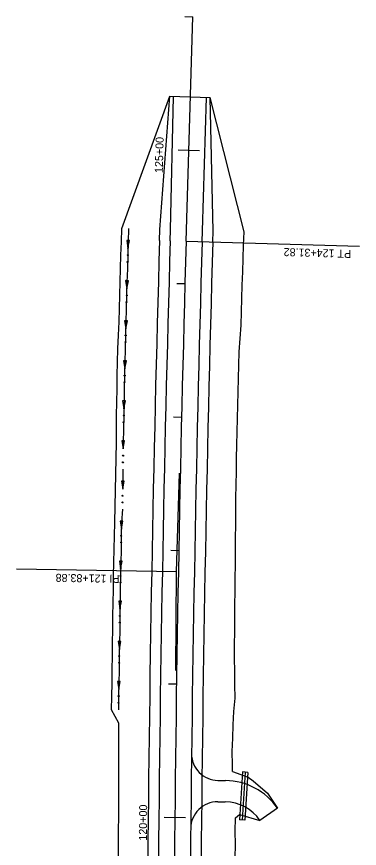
# Model space of a CAD drawing. Extents: x 1441466 to 1476381, y 2042742 to 2057194.
# Drawn here: x 1446002 to 1446259, y 2044733 to 2045357 of the extents above; entities that cross this region are included whole.
import ezdxf

# ---------------------------------------------------------------- set-up
doc = ezdxf.new("R2010")
doc.units = 0
for name, color, linetype in [('Level 43', 7, 'Continuous'), ('R_Horz Alg', 7, 'Continuous'), ('R_Horz Alg Annot', 7, 'Continuous'), ('R_Horz Alg Stationing', 7, 'Continuous'), ('R_Proposed Const Limits', 7, 'Continuous'), ('R_Proposed Road', 7, 'Continuous'), ('R_Special Ditch', 7, 'Continuous')]:
    doc.layers.add(name, color=color, linetype=linetype)

msp = doc.modelspace()

# ---------------------------------------------------------------- linework, layer by layer
at = {"layer": 'Level 43'}
for p, q in [((1446171.64, 2044790.67), (1446169.24, 2044754.75)), ((1446173.63, 2044790.54), (1446171.23, 2044754.62)), ((1446175.63, 2044790.4), (1446171.64, 2044790.67)), ((1446175.63, 2044790.4), (1446173.23, 2044754.48)), ((1446173.23, 2044754.48), (1446169.24, 2044754.75))]:
    msp.add_line(p, q, dxfattribs=at)
at = {"layer": 'R_Horz Alg'}
msp.add_line((1446129.27, 2045188.4), (1446134.17, 2045356.51), dxfattribs=at)
msp.add_arc((1469037.89, 2044521.83), 22918.31, 178.333333, 179.573112, dxfattribs=at)
at = {"layer": 'R_Horz Alg Annot'}
for p, q in [((1446122.06, 2044940.54), (1446124.22, 2045014.59)), ((1446121.51, 2044866.63), (1446122.06, 2044940.54))]:
    msp.add_line(p, q, dxfattribs=at)
for points in [[(1446129.27, 2045188.4), (1446259.22, 2045184.62)], [(1446122.06, 2044940.54), (1446002.08, 2044942.73)]]:
    msp.add_lwpolyline(points, dxfattribs=at)
at = {"layer": 'R_Horz Alg Stationing'}
for points in [[(1446128.17, 2045356.68), (1446134.17, 2045356.51)], [(1446123.26, 2045256.78), (1446139.25, 2045256.32)], [(1446122.37, 2045156.76), (1446128.37, 2045156.59)], [(1446119.82, 2045056.76), (1446125.82, 2045056.62)], [(1446117.71, 2044956.76), (1446123.7, 2044956.65)], [(1446116.03, 2044856.75), (1446122.03, 2044856.66)], [(1446112.78, 2044756.75), (1446128.78, 2044756.59)]]:
    msp.add_lwpolyline(points, dxfattribs=at)
at = {"layer": 'R_Proposed Const Limits'}
for points in [[(1446076.9, 2045037.72), (1446077.03, 2045047.74), (1446077.06, 2045057.76), (1446077.32, 2045067.78), (1446077.4, 2045077.8), (1446077.6, 2045087.82), (1446077.86, 2045097.84), (1446078, 2045107.86), (1446078.6, 2045117.87), (1446078.91, 2045127.89), (1446079.2, 2045137.9), (1446079.47, 2045147.92), (1446079.76, 2045157.94), (1446080.06, 2045167.95), (1446080.33, 2045177.97), (1446080.64, 2045187.99), (1446080.92, 2045197.99), (1446117.13, 2045296.98)], [(1446168.05, 2045065.62), (1446168.31, 2045075.6), (1446168.56, 2045085.58), (1446168.81, 2045095.56), (1446169.05, 2045105.54), (1446169.79, 2045115.5), (1446170.42, 2045125.47), (1446170.73, 2045135.45), (1446171.06, 2045145.42), (1446171.37, 2045155.4), (1446171.69, 2045165.38), (1446172.03, 2045175.35), (1446172.36, 2045185.33), (1446172.7, 2045195.32), (1446147.24, 2045296.1)], [(1446167.13, 2045025.71), (1446167.39, 2045035.68), (1446167.65, 2045045.66), (1446167.89, 2045055.64), (1446168.05, 2045065.62)], [(1446073.32, 2044837.33), (1446073.53, 2044847.35), (1446073.67, 2044857.37), (1446073.8, 2044867.39), (1446073.95, 2044877.41), (1446074.08, 2044887.43), (1446074.22, 2044897.45), (1446074.36, 2044907.47), (1446074.51, 2044917.49), (1446074.66, 2044927.51), (1446074.82, 2044937.53), (1446074.98, 2044947.55), (1446075.17, 2044957.57), (1446075.45, 2044967.58), (1446075.74, 2044977.6), (1446076.9, 2045037.72)], [(1446164.14, 2044790.94), (1446163.92, 2044796.15), (1446163.88, 2044806.14), (1446164.16, 2044816.11), (1446164.56, 2044826.09), (1446165.05, 2044836.07), (1446165.94, 2044846.04), (1446165.79, 2044856.02), (1446165.82, 2044866), (1446165.6, 2044875.99), (1446165.63, 2044885.97), (1446165.7, 2044895.95), (1446165.79, 2044905.93), (1446165.84, 2044915.91), (1446165.97, 2044925.89), (1446166.03, 2044935.88), (1446166.18, 2044945.86), (1446166.24, 2044955.84), (1446166.34, 2044965.82), (1446166.49, 2044975.8), (1446166.56, 2044985.78), (1446166.66, 2044995.76), (1446166.79, 2045005.75), (1446166.97, 2045015.73), (1446167.13, 2045025.71)], [(1446078.88, 2044767.12), (1446078.7, 2044777.14), (1446078.77, 2044787.16), (1446078.64, 2044797.18), (1446078.66, 2044807.2), (1446078.68, 2044817.21), (1446078.75, 2044827.23), (1446073.32, 2044837.33)], [(1446164.14, 2044790.94), (1446175.79, 2044786.73), (1446179.52, 2044783.99), (1446190.35, 2044774.9), (1446197.82, 2044763.46)], [(1446078.5, 2044727.04), (1446078.45, 2044737.06), (1446078.61, 2044747.08), (1446078.72, 2044757.1), (1446078.88, 2044767.12)], [(1446165.98, 2044726.26), (1446166.32, 2044736.24), (1446166.12, 2044746.22), (1446166.29, 2044756.2), (1446169.28, 2044758.72), (1446184.64, 2044754.39)]]:
    msp.add_lwpolyline(points, dxfattribs=at)
at = {"layer": 'R_Proposed Road'}
for p, q in [((1446109.52, 2045197.16), (1446117.13, 2045296.98)), ((1446117.52, 2045196.92), (1446119.67, 2045296.9)), ((1446141.51, 2045196.23), (1446144.62, 2045296.18)), ((1446149.5, 2045195.99), (1446147.24, 2045296.1)), ((1446109.28, 2045188.98), (1446109.52, 2045197.16)), ((1446117.28, 2045188.75), (1446117.52, 2045196.92)), ((1446141.27, 2045188.05), (1446141.51, 2045196.23)), ((1446149.27, 2045187.82), (1446149.5, 2045195.99)), ((1446153.1, 2044784.31), (1446158.81, 2044784.25)), ((1446152.92, 2044768.31), (1446158.63, 2044768.25)), ((1446197.82, 2044763.46), (1446184.64, 2044754.39))]:
    msp.add_line(p, q, dxfattribs=at)
msp.add_lwpolyline([(1446117.13, 2045296.98), (1446147.24, 2045296.1)], dxfattribs=at)
for centre, radius, start, end in [((1469037.89, 2044521.83), 22938.31, 178.333333, 179.573112), ((1469037.89, 2044521.83), 22930.31, 178.333333, 179.573112), ((1469037.89, 2044521.83), 22906.31, 178.333333, 179.573112), ((1469037.89, 2044521.83), 22898.31, 178.333333, 179.573112), ((1446153.32, 2044804.31), 20, 179.29279, 269.36289), ((1446158.28, 2044736.25), 48, 34.53575, 89.36289), ((1446152.7, 2044748.31), 20, 89.36289, 179.43299), ((1446158.28, 2044736.25), 32, 34.53575, 89.36289)]:
    msp.add_arc(centre, radius, start, end, dxfattribs=at)
at = {"layer": 'R_Special Ditch'}
for p, q in [((1446086.8, 2045188.81), (1446084.68, 2045188.87)), ((1446084.68, 2045188.87), (1446085.57, 2045182.85)), ((1446085.57, 2045182.85), (1446086.8, 2045188.81)), ((1446085.97, 2045158.79), (1446083.85, 2045158.85)), ((1446083.85, 2045158.85), (1446084.75, 2045152.82)), ((1446084.75, 2045152.82), (1446085.97, 2045158.79)), ((1446085.18, 2045128.76), (1446083.07, 2045128.82)), ((1446083.07, 2045128.82), (1446083.97, 2045122.79)), ((1446083.97, 2045122.79), (1446085.18, 2045128.76)), ((1446084.44, 2045098.74), (1446082.32, 2045098.79)), ((1446082.32, 2045098.79), (1446083.24, 2045092.76)), ((1446083.24, 2045092.76), (1446084.44, 2045098.74)), ((1446083.73, 2045068.71), (1446081.61, 2045068.76)), ((1446081.61, 2045068.76), (1446082.54, 2045062.73)), ((1446082.54, 2045062.73), (1446083.73, 2045068.71)), ((1446083.05, 2045038.69), (1446080.93, 2045038.71)), ((1446080.93, 2045038.71), (1446081.93, 2045032.7)), ((1446081.93, 2045032.7), (1446083.05, 2045038.69)), ((1446082.75, 2045008.65), (1446080.64, 2045008.67)), ((1446080.64, 2045008.67), (1446081.64, 2045002.66)), ((1446081.64, 2045002.66), (1446082.75, 2045008.65)), ((1446081.84, 2044978.63), (1446079.73, 2044978.67)), ((1446079.73, 2044978.67), (1446080.67, 2044972.65)), ((1446080.67, 2044972.65), (1446081.84, 2044978.63)), ((1446081.29, 2044948.6), (1446079.18, 2044948.64)), ((1446079.18, 2044948.64), (1446080.13, 2044942.62)), ((1446080.13, 2044942.62), (1446081.29, 2044948.6)), ((1446080.78, 2044918.57), (1446078.66, 2044918.6)), ((1446078.66, 2044918.6), (1446079.63, 2044912.59)), ((1446079.63, 2044912.59), (1446080.78, 2044918.57)), ((1446080.31, 2044888.54), (1446078.19, 2044888.57)), ((1446078.19, 2044888.57), (1446079.16, 2044882.55)), ((1446079.16, 2044882.55), (1446080.31, 2044888.54)), ((1446079.84, 2044858.5), (1446077.72, 2044858.54)), ((1446077.72, 2044858.54), (1446078.68, 2044852.52)), ((1446078.68, 2044852.52), (1446079.84, 2044858.5))]:
    msp.add_line(p, q, dxfattribs=at)
for points in [[(1446085.99, 2045197.84), (1446085.71, 2045187.84), (1446085.43, 2045177.83), (1446085.16, 2045167.81), (1446084.88, 2045157.8), (1446084.62, 2045147.78), (1446084.36, 2045137.76), (1446084.1, 2045127.75), (1446083.85, 2045117.73), (1446083.6, 2045107.72), (1446083.35, 2045097.7), (1446083.11, 2045087.69), (1446082.88, 2045077.67), (1446082.65, 2045067.65), (1446082.42, 2045057.64), (1446082.2, 2045047.62), (1446081.98, 2045037.6)], [(1446085.99, 2045197.84), (1446085.71, 2045187.84), (1446085.57, 2045182.85)], [(1446085.16, 2045167.81), (1446085.16, 2045167.81), (1446084.88, 2045157.8), (1446084.75, 2045152.82)], [(1446085.16, 2045167.85), (1446085.16, 2045167.81)], [(1446084.36, 2045137.79), (1446084.36, 2045137.76), (1446084.1, 2045127.75), (1446083.97, 2045122.79)], [(1446084.36, 2045137.82), (1446084.36, 2045137.79)], [(1446083.6, 2045107.76), (1446083.6, 2045107.72), (1446083.35, 2045097.7), (1446083.24, 2045092.76)], [(1446083.6, 2045107.8), (1446083.6, 2045107.76)], [(1446082.88, 2045077.73), (1446082.88, 2045077.67), (1446082.65, 2045067.65), (1446082.54, 2045062.73)], [(1446082.88, 2045077.77), (1446082.88, 2045077.73)], [(1446082.2, 2045047.7), (1446082.2, 2045047.62), (1446081.98, 2045037.6), (1446081.93, 2045032.7)], [(1446082.2, 2045047.74), (1446082.2, 2045047.7)], [(1446081.78, 2045017.66), (1446081.64, 2045002.66)], [(1446081.78, 2045017.7), (1446081.78, 2045017.66)], [(1446081.49, 2044987.51), (1446080.76, 2044977.5), (1446080.58, 2044967.48), (1446080.39, 2044957.47), (1446080.21, 2044947.45), (1446080.04, 2044937.43), (1446079.87, 2044927.42), (1446079.7, 2044917.4), (1446079.54, 2044907.38), (1446079.39, 2044897.36), (1446079.23, 2044887.34), (1446079.08, 2044877.33), (1446078.93, 2044867.31), (1446078.76, 2044857.29), (1446078.58, 2044847.27), (1446078.4, 2044837.26)], [(1446081.49, 2044987.63), (1446081.49, 2044987.51), (1446080.76, 2044977.5), (1446080.67, 2044972.65)], [(1446081.49, 2044987.67), (1446081.49, 2044987.63)], [(1446080.4, 2044957.62), (1446080.39, 2044957.47), (1446080.21, 2044947.45), (1446080.13, 2044942.62)], [(1446080.4, 2044957.66), (1446080.4, 2044957.62)], [(1446079.87, 2044927.59), (1446079.87, 2044927.42), (1446079.7, 2044917.4), (1446079.63, 2044912.59)], [(1446079.87, 2044927.62), (1446079.87, 2044927.59)], [(1446079.39, 2044897.55), (1446079.39, 2044897.36), (1446079.23, 2044887.34), (1446079.16, 2044882.55)], [(1446079.39, 2044897.59), (1446079.39, 2044897.55)], [(1446078.93, 2044867.52), (1446078.93, 2044867.31), (1446078.76, 2044857.29), (1446078.68, 2044852.52)], [(1446078.93, 2044867.56), (1446078.93, 2044867.52)], [(1446078.41, 2044837.52), (1446078.4, 2044837.48)], [(1446078.4, 2044837.48), (1446078.4, 2044837.26)]]:
    msp.add_lwpolyline(points, dxfattribs=at)
for centre in [(1446085.47, 2045177.84), (1446085.33, 2045172.83), (1446084.52, 2045142.81), (1446084.66, 2045147.81), (1446083.88, 2045117.79), (1446083.76, 2045112.78), (1446083.15, 2045087.76), (1446083.03, 2045082.75), (1446082.46, 2045057.73), (1446082.35, 2045052.72), (1446081.92, 2045027.7), (1446081.87, 2045022.69), (1446081.62, 2044997.66), (1446081.58, 2044992.65), (1446080.52, 2044962.64), (1446080.61, 2044967.65), (1446080.08, 2044937.62), (1446079.99, 2044932.61), (1446079.58, 2044907.58), (1446079.5, 2044902.57), (1446079.12, 2044877.55), (1446079.04, 2044872.54), (1446078.63, 2044847.51), (1446078.53, 2044842.5)]:
    msp.add_circle(centre, 0.375, dxfattribs=at)

# ---------------------------------------------------------------- texts
at = {"layer": 'R_Horz Alg Annot'}
for s, rotation, p in [('PT 124+31.82', 178.33333, (1446253.14, 2045181.8)), ('PI 121+83.88', 178.95322, (1446079.36, 2044938.32))]:
    msp.add_text(s, height=6, rotation=rotation, dxfattribs=at).set_placement(p)
at = {"layer": 'R_Horz Alg Stationing'}
for s, rotation, p in [('125+00', 88.33333, (1446111.68, 2045239.43)), ('120+00', 89.41289, (1446099.77, 2044739.21))]:
    msp.add_text(s, height=6, rotation=rotation, dxfattribs=at).set_placement(p)

doc.saveas('drawing.dxf')
